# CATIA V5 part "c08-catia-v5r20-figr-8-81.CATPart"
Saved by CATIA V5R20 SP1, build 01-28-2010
Part number: Part1
Bounding box of the stored display mesh (mm): x -52.625 to 52.625, y -77.625 to 77.625, z 0 to 30
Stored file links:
  D:\v5_r20\psrt_files_downloaded\c08-catia-v5r20-prt\c08-catia-v5r20-figr-8-81.CATPart
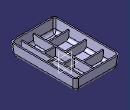
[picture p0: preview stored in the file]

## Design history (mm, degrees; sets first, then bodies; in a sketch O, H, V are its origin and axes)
Set1
  Plane1: type Offset, RefPlane xy-plane, Offset 30
  Plane2: type Offset, RefPlane face of Pad1, Offset -8, reversed
Body1 (main body)
  Sketch1 on xy-plane, origin (0, 0, 0), H (1, 0, 0), V (0, 1, 0)
    line L1 (-50, 75) -> (50, 75)
    line L2 (50, 75) -> (50, -75)
    line L3 (50, -75) -> (-50, -75)
    line L4 (-50, -75) -> (-50, 75)
    axis line L5 (50, -75) -> (-50, 75)
    length L3 = 100
    length L2 = 150
    horizontal: L1 H, L3 H
    vertical: L2 V, L4 V
    midpoint: O L5
  Pad1: profile Sketch1, direction (0, 0, 1), length 0, opposite side up to Plane1
  Draft1: PullDir face of Pad1, Angle -5, SupportToDraft (face of Pad1; face of Pad1; face of Pad1; face of Pad1), Neutral face of Pad1
  Fillet1: radius 7, on edge [face of Pad1 | face of Pad1] (x4)
  Fillet2: radius 10, on edge [face of Pad1 | face of Pad1] (x4)
  Shell1: IntOffset 3, Face face of Pad1, ExtOffset 0
  Sketch2 on Plane2, origin (0, 0, 22), H (1, 0, 0), V (0, -1, 0)
    line L1 (28.1747, 54.0191) -> (28.1747, -59.2866)
    line L2 (0, 54.0191) -> (0, -59.2866)
    point P3 (0, 54.0191)
    line L3 (-9.5939, 0) -> (-33.0562, 0)
    point P5 (-9.5939, 0)
    line L4 (-9.5939, -40.4023) -> (-33.0562, -40.4023)
    point P7 (-9.5939, -40.4023)
    point P8 (-33.0562, -40.4023)
    point P9 (-33.0562, 40.4023)
    point P10 (-9.5939, 40.4023)
    line L5 (-9.5939, 40.4023) -> (-33.0562, 40.4023)
    line L6 (28.1747, 22.6983) -> (0, 22.6983)
    point P11 (28.1747, 22.6983)
    point P12 (0, 22.6983)
    point P13 (0, -22.6983)
    point P14 (28.1747, -22.6983)
    line L7 (28.1747, -22.6983) -> (0, -22.6983)
    line L8 (28.1747, 0) -> (41.8849, 0)
    point P15 (28.1747, 0)
    vertical: L1 V, L2 V
    coincidence: P3 V, P5 H, P11 L1, P12 L2, P15 L1, P15 H
    horizontal: L3 H, L4 H, L6 H, L8 H
    symmetry: P8 P9 L3, P7 P10 L3, L4 L5 L3, P12 P13 H, P11 P14 H, L6 L7 H
  Stiffener1: ThicknessValue 3, ExtendedProfile Sketch2, ThicknessTop 1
